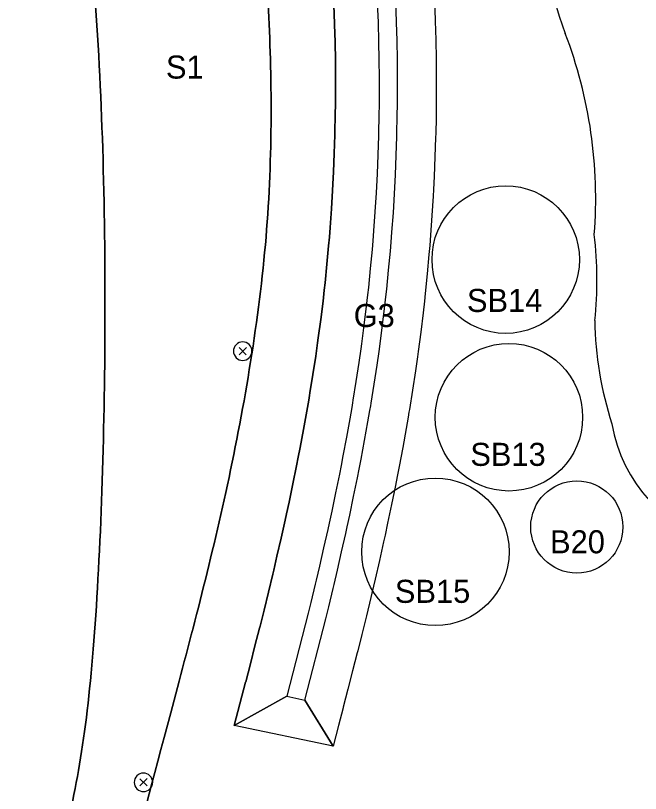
# Model space of a CAD drawing. Extents: x 0 to 512122, y 0 to 6212554.
# Drawn here: x 511726.32 to 511760.22, y 6211681.8 to 6211723.97 of the extents above; entities that cross this region are included whole.
import ezdxf

# ---------------------------------------------------------------- set-up
doc = ezdxf.new("R2010")
doc.units = 0
for name, color, linetype in [('_lights', 7, 'Continuous'), ('_S1_rabarber', 7, 'Continuous'), ('L40 jord udlagt muld og grøft', 7, 'Continuous'), ('TV_U_AFM_Symbl_Gul', 7, 'Continuous'), ('TV_U_LYS_Mastenummer', 7, 'Continuous'), ('TV_U_LYS_Nyx330-Trafiksti-x2', 7, 'Continuous')]:
    doc.layers.add(name, color=color, linetype=linetype)

msp = doc.modelspace()

# ---------------------------------------------------------------- linework, layer by layer
at = {"layer": '_lights'}
for p, q in [((511738.443, 6211705.97), (511738.837, 6211705.575)), ((511738.841, 6211705.974), (511738.447, 6211705.579)), ((511733.059, 6211682.596), (511733.453, 6211682.202)), ((511733.457, 6211682.6), (511733.063, 6211682.206))]:
    msp.add_line(p, q, dxfattribs=at)
for centre, start, end in [((511738.64, 6211705.773), 315.5636, 315), ((511738.64, 6211705.773), 315, 315.5636), ((511733.256, 6211682.399), 315.5636, 315), ((511733.256, 6211682.399), 315, 315.5636)]:
    msp.add_arc(centre, 0.5, start, end, dxfattribs=at)
at = {"layer": '_S1_rabarber'}
for points in [[(511734.603, 6211757.422), (511735.331, 6211754.157), (511736.949, 6211746.893), (511739.141, 6211736.177), (511740.137, 6211725.286), (511740.362, 6211712.579), (511738.054, 6211698.643), (511734.81, 6211686.446), (511733.067, 6211679.907), (511732.568, 6211678.04)], [(511732.568, 6211678.04), (511733.067, 6211679.907), (511734.81, 6211686.446), (511738.054, 6211698.643), (511740.362, 6211712.579), (511740.137, 6211725.286), (511739.141, 6211736.177), (511736.949, 6211746.893), (511735.331, 6211754.157), (511734.603, 6211757.422)], [(511726.316, 6211673.166), (511726.701, 6211673.84), (511729.166, 6211678.46), (511730.77, 6211689.196), (511731.359, 6211707.945), (511730.809, 6211726.91), (511728.592, 6211740.772), (511727.934, 6211745.488), (511727.864, 6211745.992)], [(511727.864, 6211745.992), (511727.934, 6211745.488), (511728.592, 6211740.772), (511730.809, 6211726.91), (511731.359, 6211707.945), (511730.77, 6211689.196), (511729.166, 6211678.46), (511726.701, 6211673.84), (511726.316, 6211673.166)]]:
    msp.add_open_spline(points, degree=3, dxfattribs=at)
at = {"layer": 'L40 jord udlagt muld og grøft'}
for points in [[(511745.944, 6211724.639), (511745.984, 6211723.612), (511745.986, 6211723.558), (511746.013, 6211722.583), (511746.033, 6211721.555), (511746.041, 6211720.607), (511746.042, 6211720.526), (511746.04, 6211719.498), (511746.038, 6211719.24), (511746.028, 6211718.469), (511746.012, 6211717.655), (511746.006, 6211717.441), (511745.974, 6211716.412), (511745.932, 6211715.385), (511745.898, 6211714.705), (511745.879, 6211714.357), (511745.816, 6211713.331), (511745.742, 6211712.305), (511745.699, 6211711.76), (511745.659, 6211711.279), (511745.565, 6211710.255), (511745.461, 6211709.232), (511745.416, 6211708.822), (511745.347, 6211708.209), (511745.222, 6211707.188), (511745.087, 6211706.169), (511745.049, 6211705.893), (511744.943, 6211705.151), (511744.788, 6211704.135), (511744.624, 6211703.122), (511744.6, 6211702.978), (511744.557, 6211702.722), (511744.451, 6211702.112), (511744.27, 6211701.104), (511744.081, 6211700.099), (511743.98, 6211699.577), (511743.885, 6211699.097), (511743.681, 6211698.097), (511743.471, 6211697.099), (511743.332, 6211696.457), (511743.255, 6211696.105), (511743.032, 6211695.112), (511742.804, 6211694.122), (511742.626, 6211693.361), (511742.572, 6211693.135), (511742.334, 6211692.15), (511742.193, 6211691.575), (511741.039, 6211687.066), (511738.183, 6211685.486), (511738.797, 6211687.821), (511738.806, 6211687.853), (511739.058, 6211688.822), (511739.308, 6211689.792), (511739.555, 6211690.763), (511739.58, 6211690.865), (511739.798, 6211691.735), (511740.037, 6211692.709), (511740.271, 6211693.683), (511740.324, 6211693.907), (511740.501, 6211694.659), (511740.726, 6211695.636), (511740.945, 6211696.615), (511741.022, 6211696.962), (511741.159, 6211697.595), (511741.366, 6211698.577), (511741.566, 6211699.56), (511741.659, 6211700.032), (511741.759, 6211700.545), (511741.945, 6211701.532), (511742.122, 6211702.52), (511742.225, 6211703.118), (511742.268, 6211703.369), (511742.291, 6211703.51), (511742.452, 6211704.502), (511742.603, 6211705.495), (511742.707, 6211706.22), (511742.744, 6211706.49), (511742.876, 6211707.486), (511742.998, 6211708.484), (511743.066, 6211709.082), (511743.109, 6211709.483), (511743.211, 6211710.483), (511743.303, 6211711.483), (511743.342, 6211711.953), (511743.384, 6211712.485), (511743.456, 6211713.488), (511743.518, 6211714.491), (511743.536, 6211714.83), (511743.569, 6211715.494), (511743.611, 6211716.498), (511743.642, 6211717.503), (511743.648, 6211717.712), (511743.664, 6211718.508), (511743.673, 6211719.261), (511743.675, 6211719.513), (511743.677, 6211720.518), (511743.676, 6211720.596), (511743.668, 6211721.523), (511743.649, 6211722.527), (511743.622, 6211723.48), (511743.62, 6211723.532), (511743.582, 6211724.536)], [(511743.582, 6211724.536), (511743.62, 6211723.532), (511743.622, 6211723.48), (511743.649, 6211722.527), (511743.668, 6211721.523), (511743.676, 6211720.596), (511743.677, 6211720.518), (511743.675, 6211719.513), (511743.673, 6211719.261), (511743.664, 6211718.508), (511743.648, 6211717.712), (511743.642, 6211717.503), (511743.611, 6211716.498), (511743.569, 6211715.494), (511743.536, 6211714.83), (511743.518, 6211714.491), (511743.456, 6211713.488), (511743.384, 6211712.485), (511743.342, 6211711.953), (511743.303, 6211711.483), (511743.211, 6211710.483), (511743.109, 6211709.483), (511743.066, 6211709.082), (511742.998, 6211708.484), (511742.876, 6211707.486), (511742.744, 6211706.49), (511742.707, 6211706.22), (511742.603, 6211705.495), (511742.452, 6211704.502), (511742.291, 6211703.51), (511742.268, 6211703.369), (511742.225, 6211703.118), (511742.122, 6211702.52), (511741.945, 6211701.532), (511741.759, 6211700.545), (511741.659, 6211700.032), (511741.566, 6211699.56), (511741.366, 6211698.577), (511741.159, 6211697.595), (511741.022, 6211696.962), (511740.945, 6211696.615), (511740.726, 6211695.636), (511740.501, 6211694.659), (511740.324, 6211693.907), (511740.271, 6211693.683), (511740.037, 6211692.709), (511739.798, 6211691.735), (511739.58, 6211690.865), (511739.555, 6211690.763), (511739.308, 6211689.792), (511739.058, 6211688.822), (511738.806, 6211687.853), (511738.797, 6211687.821), (511738.183, 6211685.486)], [(511745.944, 6211724.639), (511745.984, 6211723.612), (511745.986, 6211723.558), (511746.013, 6211722.583), (511746.033, 6211721.555), (511746.041, 6211720.607), (511746.042, 6211720.526), (511746.04, 6211719.498), (511746.038, 6211719.24), (511746.028, 6211718.469), (511746.012, 6211717.655), (511746.006, 6211717.441), (511745.974, 6211716.412), (511745.932, 6211715.385), (511745.898, 6211714.705), (511745.879, 6211714.357), (511745.816, 6211713.331), (511745.742, 6211712.305), (511745.699, 6211711.76), (511745.659, 6211711.279), (511745.565, 6211710.255), (511745.461, 6211709.232), (511745.416, 6211708.822), (511745.347, 6211708.209), (511745.222, 6211707.188), (511745.087, 6211706.169), (511745.049, 6211705.893), (511744.943, 6211705.151), (511744.788, 6211704.135), (511744.624, 6211703.122), (511744.6, 6211702.978), (511744.557, 6211702.722), (511744.451, 6211702.112), (511744.27, 6211701.104), (511744.081, 6211700.099), (511743.98, 6211699.577), (511743.885, 6211699.097), (511743.681, 6211698.097), (511743.471, 6211697.099), (511743.332, 6211696.457), (511743.255, 6211696.105), (511743.032, 6211695.112), (511742.804, 6211694.122), (511742.626, 6211693.361), (511742.572, 6211693.135), (511742.334, 6211692.15), (511742.193, 6211691.575), (511741.039, 6211687.066), (511742.011, 6211686.858), (511743.144, 6211691.256), (511743.162, 6211691.328), (511743.306, 6211691.913), (511743.545, 6211692.903), (511743.599, 6211693.13), (511743.778, 6211693.896), (511744.007, 6211694.891), (511744.231, 6211695.889), (511744.309, 6211696.243), (511744.449, 6211696.89), (511744.661, 6211697.894), (511744.866, 6211698.901), (511744.961, 6211699.384), (511745.063, 6211699.91), (511745.254, 6211700.923), (511745.436, 6211701.939), (511745.543, 6211702.554), (511745.586, 6211702.813), (511745.611, 6211702.958), (511745.776, 6211703.98), (511745.932, 6211705.005), (511746.039, 6211705.754), (511746.078, 6211706.033), (511746.214, 6211707.062), (511746.34, 6211708.093), (511746.41, 6211708.711), (511746.455, 6211709.126), (511746.56, 6211710.159), (511746.655, 6211711.193), (511746.696, 6211711.678), (511746.74, 6211712.228), (511746.814, 6211713.264), (511746.877, 6211714.301), (511746.896, 6211714.652), (511746.931, 6211715.338), (511746.974, 6211716.376), (511747.006, 6211717.414), (511747.012, 6211717.631), (511747.028, 6211718.453), (511747.038, 6211719.231), (511747.04, 6211719.491), (511747.042, 6211720.53), (511747.041, 6211720.611), (511747.033, 6211721.568), (511747.013, 6211722.607), (511746.985, 6211723.591), (511746.983, 6211723.645), (511746.943, 6211724.683)], [(511749.043, 6211724.775), (511749.084, 6211723.716), (511749.086, 6211723.661), (511749.115, 6211722.657), (511749.134, 6211721.597), (511749.143, 6211720.62), (511749.144, 6211720.538), (511749.142, 6211719.478), (511749.14, 6211719.212), (511749.13, 6211718.418), (511749.113, 6211717.579), (511749.107, 6211717.359), (511749.074, 6211716.3), (511749.03, 6211715.241), (511748.996, 6211714.541), (511748.976, 6211714.183), (511748.911, 6211713.125), (511748.836, 6211712.068), (511748.791, 6211711.507), (511748.749, 6211711.012), (511748.653, 6211709.957), (511748.546, 6211708.902), (511748.5, 6211708.48), (511748.428, 6211707.849), (511748.299, 6211706.797), (511748.161, 6211705.747), (511748.121, 6211705.463), (511748.011, 6211704.698), (511747.852, 6211703.654), (511747.684, 6211702.613), (511747.66, 6211702.465), (511747.615, 6211702.202), (511747.507, 6211701.576), (511747.321, 6211700.543), (511747.128, 6211699.514), (511747.024, 6211698.979), (511746.927, 6211698.489), (511746.719, 6211697.467), (511746.504, 6211696.449), (511746.362, 6211695.794), (511746.284, 6211695.436), (511746.057, 6211694.425), (511745.826, 6211693.419), (511745.644, 6211692.645), (511745.589, 6211692.416), (511745.349, 6211691.416), (511745.104, 6211690.42), (511744.882, 6211689.531), (511744.856, 6211689.427), (511744.605, 6211688.438), (511744.351, 6211687.451), (511744.094, 6211686.468), (511744.086, 6211686.436), (511743.836, 6211685.488), (511743.554, 6211684.357), (511742.011, 6211686.858), (511743.144, 6211691.256), (511743.162, 6211691.328), (511743.306, 6211691.913), (511743.545, 6211692.903), (511743.599, 6211693.13), (511743.778, 6211693.896), (511744.007, 6211694.891), (511744.231, 6211695.889), (511744.309, 6211696.243), (511744.449, 6211696.89), (511744.661, 6211697.894), (511744.866, 6211698.901), (511744.961, 6211699.384), (511745.063, 6211699.91), (511745.254, 6211700.923), (511745.436, 6211701.939), (511745.543, 6211702.554), (511745.586, 6211702.813), (511745.611, 6211702.958), (511745.776, 6211703.98), (511745.932, 6211705.005), (511746.039, 6211705.754), (511746.078, 6211706.033), (511746.214, 6211707.062), (511746.34, 6211708.093), (511746.41, 6211708.711), (511746.455, 6211709.126), (511746.56, 6211710.159), (511746.655, 6211711.193), (511746.696, 6211711.678), (511746.74, 6211712.228), (511746.814, 6211713.264), (511746.877, 6211714.301), (511746.896, 6211714.652), (511746.931, 6211715.338), (511746.974, 6211716.376), (511747.006, 6211717.414), (511747.012, 6211717.631), (511747.028, 6211718.453), (511747.038, 6211719.231), (511747.04, 6211719.491), (511747.042, 6211720.53), (511747.041, 6211720.611), (511747.033, 6211721.568), (511747.013, 6211722.607), (511746.985, 6211723.591), (511746.983, 6211723.645), (511746.943, 6211724.683)], [(511749.043, 6211724.775), (511749.084, 6211723.716), (511749.086, 6211723.661), (511749.115, 6211722.657), (511749.134, 6211721.597), (511749.143, 6211720.62), (511749.144, 6211720.538), (511749.142, 6211719.478), (511749.14, 6211719.212), (511749.13, 6211718.418), (511749.113, 6211717.579), (511749.107, 6211717.359), (511749.074, 6211716.3), (511749.03, 6211715.241), (511748.996, 6211714.541), (511748.976, 6211714.183), (511748.911, 6211713.125), (511748.836, 6211712.068), (511748.791, 6211711.507), (511748.749, 6211711.012), (511748.653, 6211709.957), (511748.546, 6211708.902), (511748.5, 6211708.48), (511748.428, 6211707.849), (511748.299, 6211706.797), (511748.161, 6211705.747), (511748.121, 6211705.463), (511748.011, 6211704.698), (511747.852, 6211703.654), (511747.684, 6211702.613), (511747.66, 6211702.465), (511747.615, 6211702.202), (511747.507, 6211701.576), (511747.321, 6211700.543), (511747.128, 6211699.514), (511747.024, 6211698.979), (511746.927, 6211698.489), (511746.719, 6211697.467), (511746.504, 6211696.449), (511746.362, 6211695.794), (511746.284, 6211695.436), (511746.057, 6211694.425), (511745.826, 6211693.419), (511745.644, 6211692.645), (511745.589, 6211692.416), (511745.349, 6211691.416), (511745.104, 6211690.42), (511744.882, 6211689.531), (511744.856, 6211689.427), (511744.605, 6211688.438), (511744.351, 6211687.451), (511744.094, 6211686.468), (511744.089, 6211686.448), (511744.086, 6211686.436), (511743.836, 6211685.488), (511743.554, 6211684.357)]]:
    msp.add_lwpolyline(points, dxfattribs=at)
msp.add_lwpolyline([(511742.011, 6211686.858), (511743.554, 6211684.357), (511738.183, 6211685.486), (511741.039, 6211687.066)], close=True, dxfattribs=at)
at = {"layer": 'TV_U_LYS_Mastenummer'}
for centre, radius in [((511752.912, 6211710.737), 4), ((511752.912, 6211710.737), 4), ((511753.086, 6211702.19), 4), ((511753.086, 6211702.19), 4), ((511749.097, 6211694.894), 4), ((511749.097, 6211694.894), 4), ((511756.769, 6211696.242), 2.5), ((511756.769, 6211696.242), 2.5)]:
    msp.add_circle(centre, radius, dxfattribs=at)
at = {"layer": 'TV_U_LYS_Nyx330-Trafiksti-x2'}
for centre, radius, start, end in [((511774.615, 6211730.061), 19.777, 155.028, 200.9233), ((511732.726, 6211714.046), 25.069, 355.5228, 20.9233), ((511737.387, 6211709.646), 20.478, 353.8058, 6.8529), ((511776.664, 6211707.69), 18.92, 180.7675, 198.0363), ((511766.63, 6211703.16), 8.067, 189.4784, 256.1182)]:
    msp.add_arc(centre, radius, start, end, dxfattribs=at)

# ---------------------------------------------------------------- texts
at = {"layer": 'TV_U_AFM_Symbl_Gul'}
for s, p in [('S1', (511734.477, 6211720.551)), ('SB14', (511750.809, 6211707.899)), ('G3', (511744.663, 6211707.08)), ('SB13', (511750.993, 6211699.554)), ('B20', (511755.319, 6211694.814)), ('SB15', (511746.898, 6211692.128))]:
    msp.add_text(s, height=1.25, dxfattribs=at).set_placement(p)

doc.saveas('drawing.dxf')
